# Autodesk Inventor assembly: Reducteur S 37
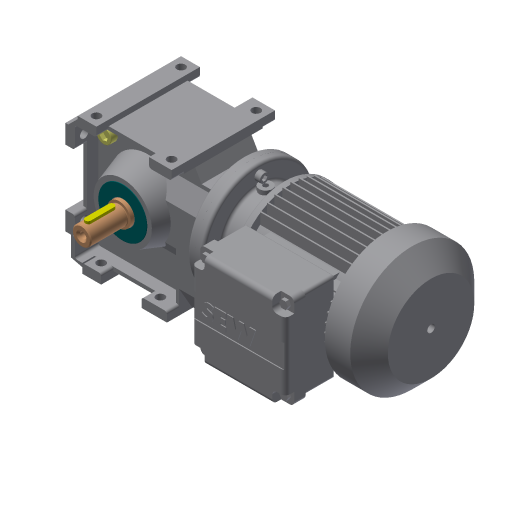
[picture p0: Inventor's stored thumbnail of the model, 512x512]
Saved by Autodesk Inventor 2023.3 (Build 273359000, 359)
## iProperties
Created: 2012-12
Part Number: Reducteur S 37
Document SubType Name: Assembly
Designer: jost thierry
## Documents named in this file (9)
- E:\Dossier technique\Reducteur\TD02-Reducteur S37\TD02-Reducteur-Ressources\TD02-Reduct-3D\TD02- Reducteur S 37.iam
- E:\Dossier technique\Reducteur\TD02-Reducteur S37\TD02-Reducteur-Ressources\TD02-Reduct-3D\bati.ipt
- E:\Dossier technique\Reducteur\TD02-Reducteur S37\TD02-Reducteur-Ressources\TD02-Reduct-3D\arbre sortie.iam
- E:\Dossier technique\Reducteur\TD02-Reducteur S37\TD02-Reducteur-Ressources\TD02-Reduct-3D\vis sans fin.iam
- E:\Dossier technique\Reducteur\TD02-Reducteur S37\TD02-Reducteur-Ressources\TD02-Reduct-3D\ROUE 1.ipt
- E:\Dossier technique\Reducteur\TD02-Reducteur S37\TD02-Reducteur-Ressources\TD02-Reduct-3D\bouchon2.ipt
- E:\Dossier technique\Reducteur\TD02-Reducteur S37\TD02-Reducteur-Ressources\TD02-Reduct-3D\BOUCHON VIDANGE.ipt
- E:\Dossier technique\Reducteur\TD02-Reducteur S37\TD02-Reducteur-Ressources\TD02-Reduct-3D\moteur.iam
- E:\Dossier technique\Reducteur\TD02-Reducteur S37\TD02-Reducteur-Ressources\TD02-Reduct-3D\Vis CHC M6-12 - 4.8, Grade A, type 2 - NF E 25-125.ipt
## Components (12 placed, 8 different names)
1. bati:1
2. arbre sortie:1 [sub-assembly]
3. vis sans fin:1 [sub-assembly]
4. ROUE 1:2
5. bouchon2:1
6. bouchon2:2
7. BOUCHON VIDANGE:1
8. moteur:1 [sub-assembly]
9. Vis CHC M6-12 - 4.8, Grade A, type 2 - NF E 25-125:1
10. Vis CHC M6-12 - 4.8, Grade A, type 2 - NF E 25-125:2
11. Vis CHC M6-12 - 4.8, Grade A, type 2 - NF E 25-125:3
12. Vis CHC M6-12 - 4.8, Grade A, type 2 - NF E 25-125:4
